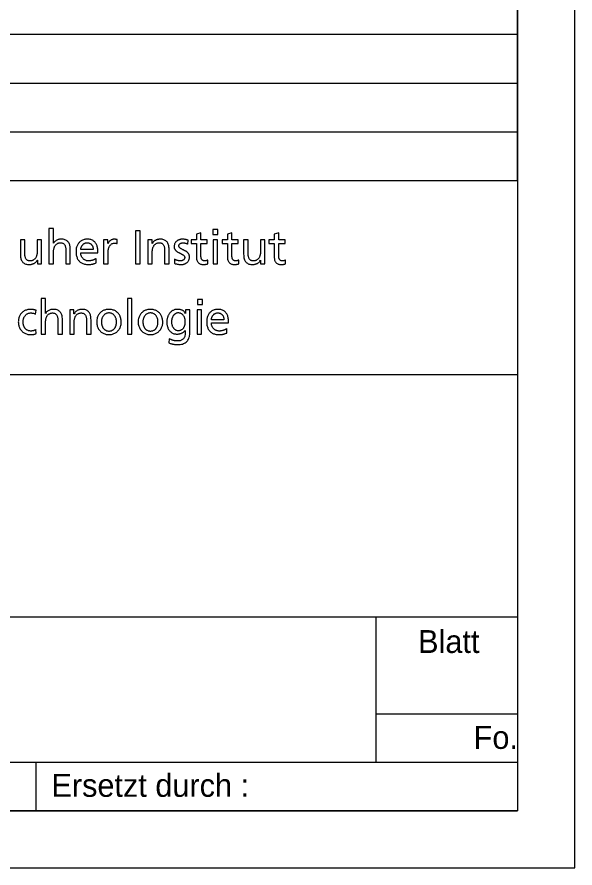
# Model space of a CAD drawing. Extents: x 0 to 210, y 0 to 148.
# Drawn here: x 198.08 to 210.25, y 0 to 18.56 of the extents above; entities that cross this region are included whole.
import ezdxf

# ---------------------------------------------------------------- set-up
doc = ezdxf.new("R2010")
doc.units = 0
doc.layers.add('90_Plankopf', color=7, linetype='Continuous')

msp = doc.modelspace()

# ---------------------------------------------------------------- linework, layer by layer
at = {"layer": '90_Plankopf'}
for p, q in [((209, 14.998), (209, 28.745)), ((164.53, 18.185), (209, 18.185)), ((164.53, 17.123), (209, 17.123)), ((164.53, 16.06), (209, 16.06)), ((164.53, 14.998), (209, 14.998)), ((164.53, 14.998), (209, 14.998)), ((209, 14.998), (209, 1.25)), ((209, 14.998), (209, 1.25)), ((200.264, 13.621), (200.264, 13.708)), ((201.808, 13.61), (201.816, 13.694)), ((199.743, 13.49), (199.471, 13.49)), ((199.471, 13.418), (199.846, 13.418)), ((199.806, 13.198), (199.806, 13.295)), ((201.518, 13.28), (201.513, 13.193)), ((202.24, 13.179), (202.24, 13.261)), ((202.916, 13.179), (202.916, 13.261)), ((203.936, 13.179), (203.936, 13.261)), ((198.488, 12.084), (198.496, 12.165)), ((202.593, 11.96), (202.321, 11.96)), ((202.321, 11.888), (202.696, 11.888)), ((198.5, 11.656), (198.493, 11.743)), ((202.656, 11.668), (202.656, 11.765)), ((201.399, 11.543), (201.389, 11.454)), ((188, 10.768), (209, 10.768)), ((188, 5.48), (209, 5.48)), ((205.912, 2.308), (205.912, 5.48)), ((205.912, 3.365), (209, 3.365)), ((188, 2.308), (209, 2.308)), ((198.5, 1.25), (198.5, 2.308)), ((209, 1.25), (164.53, 1.25)), ((167.45, 1.25), (209, 1.25)), ((167.45, 1.25), (209, 1.25))]:
    msp.add_line(p, q, dxfattribs=at)
for points in [[(0, 0), (210.25, 0), (210.25, 148.5), (0, 148.5)], [(6.25, 147.25), (209, 147.25), (209, 1.25), (6.25, 1.25)]]:
    msp.add_lwpolyline(points, close=True, dxfattribs=at)
for points in [[(198.877, 13.627), (198.875, 13.627), (198.875, 13.95), (198.778, 13.95), (198.778, 13.176), (198.875, 13.176), (198.875, 13.42)], [(202.463, 13.82), (202.463, 13.93), (202.354, 13.93), (202.354, 13.82), (202.463, 13.82)], [(200.662, 13.176), (200.765, 13.176), (200.765, 13.897), (200.662, 13.897), (200.662, 13.176)], [(202.093, 13.336), (202.093, 13.624), (202.232, 13.624), (202.232, 13.703), (202.093, 13.703), (202.093, 13.855), (201.996, 13.824), (201.996, 13.703), (201.877, 13.703), (201.877, 13.624), (201.996, 13.624), (201.996, 13.317)], [(202.769, 13.336), (202.769, 13.624), (202.908, 13.624), (202.908, 13.703), (202.769, 13.703), (202.769, 13.855), (202.672, 13.824), (202.672, 13.703), (202.553, 13.703), (202.553, 13.624), (202.672, 13.624), (202.672, 13.317)], [(203.788, 13.336), (203.788, 13.624), (203.928, 13.624), (203.928, 13.703), (203.788, 13.703), (203.788, 13.855), (203.691, 13.824), (203.691, 13.703), (203.573, 13.703), (203.573, 13.624), (203.691, 13.624), (203.691, 13.317)], [(198.251, 13.43), (198.251, 13.703), (198.154, 13.703), (198.154, 13.39)], [(198.523, 13.26), (198.525, 13.26), (198.525, 13.176), (198.619, 13.176), (198.619, 13.703), (198.522, 13.703), (198.522, 13.459)], [(200.063, 13.621), (200.061, 13.621), (200.061, 13.703), (199.97, 13.703), (199.97, 13.176), (200.067, 13.176), (200.067, 13.416)], [(201.029, 13.619), (201.027, 13.619), (201.027, 13.703), (200.933, 13.703), (200.933, 13.176), (201.03, 13.176), (201.03, 13.42)], [(202.36, 13.703), (202.36, 13.176), (202.457, 13.176), (202.457, 13.703), (202.36, 13.703)], [(203.121, 13.43), (203.121, 13.703), (203.024, 13.703), (203.024, 13.39)], [(203.393, 13.26), (203.395, 13.26), (203.395, 13.176), (203.489, 13.176), (203.489, 13.703), (203.392, 13.703), (203.392, 13.459)], [(199.147, 13.449), (199.147, 13.176), (199.244, 13.176), (199.244, 13.489)], [(201.301, 13.449), (201.301, 13.176), (201.398, 13.176), (201.398, 13.489)], [(198.705, 12.097), (198.703, 12.097), (198.703, 12.42), (198.606, 12.42), (198.606, 11.647), (198.703, 11.647), (198.703, 11.89)], [(200.491, 11.647), (200.588, 11.647), (200.588, 12.42), (200.491, 12.42), (200.491, 11.647)], [(202.123, 12.29), (202.123, 12.4), (202.014, 12.4), (202.014, 12.29), (202.123, 12.29)], [(199.326, 12.089), (199.324, 12.089), (199.324, 12.173), (199.23, 12.173), (199.23, 11.647), (199.327, 11.647), (199.327, 11.89)], [(201.849, 11.669), (201.849, 12.173), (201.759, 12.173), (201.759, 12.094), (201.757, 12.094)], [(202.008, 12.173), (202.008, 11.647), (202.105, 11.647), (202.105, 12.173), (202.008, 12.173)], [(198.974, 11.919), (198.974, 11.647), (199.071, 11.647), (199.071, 11.959)], [(199.598, 11.919), (199.598, 11.647), (199.695, 11.647), (199.695, 11.959)], [(201.75, 11.728), (201.752, 11.728), (201.752, 11.677)]]:
    msp.add_lwpolyline(points, dxfattribs=at)
for points in [[(198.875, 13.42), (198.875, 13.452), (198.878, 13.481), (198.885, 13.508), (198.891, 13.534), (198.901, 13.557), (198.914, 13.576), (198.927, 13.595), (198.944, 13.61), (198.964, 13.621), (198.984, 13.631), (199.008, 13.636), (199.035, 13.637), (199.063, 13.635), (199.085, 13.627), (199.102, 13.613), (199.118, 13.599), (199.13, 13.578), (199.137, 13.551), (199.144, 13.524), (199.147, 13.49), (199.147, 13.449)], [(199.244, 13.489), (199.244, 13.536), (199.237, 13.577), (199.223, 13.61), (199.209, 13.644), (199.187, 13.67), (199.158, 13.688), (199.129, 13.706), (199.092, 13.715), (199.047, 13.715), (199.01, 13.715), (198.977, 13.707), (198.948, 13.692), (198.919, 13.677), (198.895, 13.655), (198.877, 13.627)], [(199.846, 13.418), (199.846, 13.46), (199.842, 13.5), (199.835, 13.536), (199.827, 13.572), (199.814, 13.603), (199.796, 13.63), (199.778, 13.657), (199.754, 13.677), (199.724, 13.692), (199.695, 13.707), (199.658, 13.715), (199.614, 13.715), (199.577, 13.715), (199.543, 13.708), (199.513, 13.695), (199.483, 13.682), (199.457, 13.664), (199.435, 13.64), (199.414, 13.617), (199.397, 13.589), (199.385, 13.556), (199.374, 13.524), (199.368, 13.488), (199.368, 13.449), (199.368, 13.406), (199.373, 13.367), (199.384, 13.332), (199.395, 13.297), (199.411, 13.267), (199.434, 13.242), (199.456, 13.217), (199.484, 13.198), (199.519, 13.184), (199.553, 13.171), (199.593, 13.164), (199.64, 13.164), (199.669, 13.164), (199.693, 13.166), (199.713, 13.17), (199.733, 13.174), (199.751, 13.178), (199.766, 13.183), (199.78, 13.188), (199.794, 13.193), (199.806, 13.198)], [(199.471, 13.49), (199.472, 13.507), (199.476, 13.524), (199.483, 13.542), (199.489, 13.559), (199.497, 13.574), (199.509, 13.589), (199.52, 13.603), (199.534, 13.615), (199.551, 13.623), (199.568, 13.632), (199.588, 13.636), (199.612, 13.637), (199.633, 13.636), (199.652, 13.633), (199.668, 13.625), (199.684, 13.617), (199.698, 13.607), (199.709, 13.594), (199.72, 13.58), (199.729, 13.564), (199.734, 13.547), (199.74, 13.529), (199.743, 13.51), (199.743, 13.49)], [(200.264, 13.708), (200.258, 13.709), (200.251, 13.71), (200.245, 13.712), (200.239, 13.713), (200.232, 13.713), (200.225, 13.714), (200.218, 13.715), (200.21, 13.715), (200.2, 13.715), (200.182, 13.715), (200.163, 13.711), (200.146, 13.703), (200.128, 13.695), (200.112, 13.684), (200.098, 13.67), (200.083, 13.656), (200.072, 13.639), (200.063, 13.621)], [(200.067, 13.416), (200.067, 13.46), (200.073, 13.498), (200.085, 13.53), (200.097, 13.562), (200.113, 13.587), (200.135, 13.604), (200.156, 13.621), (200.182, 13.63), (200.211, 13.63), (200.219, 13.631), (200.228, 13.63), (200.237, 13.629), (200.246, 13.627), (200.255, 13.625), (200.264, 13.621)], [(201.398, 13.489), (201.398, 13.536), (201.391, 13.577), (201.377, 13.61), (201.364, 13.644), (201.342, 13.67), (201.313, 13.688), (201.284, 13.706), (201.247, 13.715), (201.201, 13.715), (201.177, 13.715), (201.153, 13.711), (201.13, 13.704), (201.108, 13.696), (201.088, 13.685), (201.07, 13.67), (201.053, 13.656), (201.039, 13.639), (201.029, 13.619)], [(201.03, 13.42), (201.03, 13.452), (201.033, 13.481), (201.039, 13.508), (201.046, 13.534), (201.055, 13.557), (201.069, 13.576), (201.082, 13.595), (201.098, 13.61), (201.118, 13.621), (201.138, 13.631), (201.162, 13.636), (201.19, 13.637), (201.218, 13.635), (201.24, 13.627), (201.256, 13.613), (201.273, 13.599), (201.284, 13.578), (201.291, 13.551), (201.298, 13.524), (201.301, 13.49), (201.301, 13.449)], [(201.816, 13.694), (201.797, 13.7), (201.778, 13.705), (201.759, 13.709), (201.739, 13.713), (201.718, 13.715), (201.696, 13.715), (201.669, 13.715), (201.645, 13.712), (201.623, 13.705), (201.6, 13.698), (201.581, 13.688), (201.564, 13.675), (201.547, 13.662), (201.534, 13.645), (201.524, 13.625), (201.515, 13.604), (201.51, 13.58), (201.51, 13.553), (201.51, 13.532), (201.514, 13.514), (201.523, 13.498), (201.531, 13.483), (201.541, 13.47), (201.555, 13.459), (201.569, 13.447), (201.583, 13.437), (201.6, 13.429), (201.616, 13.42), (201.632, 13.412), (201.648, 13.404), (201.664, 13.397), (201.679, 13.389), (201.693, 13.38), (201.706, 13.373), (201.717, 13.363), (201.725, 13.353), (201.733, 13.343), (201.738, 13.331), (201.738, 13.318), (201.738, 13.304), (201.735, 13.292), (201.729, 13.282), (201.723, 13.272), (201.715, 13.265), (201.705, 13.259), (201.695, 13.253), (201.685, 13.249), (201.673, 13.246), (201.662, 13.244), (201.65, 13.242), (201.639, 13.242), (201.629, 13.242), (201.617, 13.244), (201.604, 13.247), (201.59, 13.249), (201.575, 13.253), (201.56, 13.259), (201.545, 13.265), (201.531, 13.271), (201.518, 13.28)], [(201.513, 13.193), (201.535, 13.181), (201.559, 13.174), (201.583, 13.17), (201.608, 13.166), (201.632, 13.164), (201.657, 13.164), (201.681, 13.164), (201.704, 13.167), (201.726, 13.174), (201.747, 13.18), (201.767, 13.191), (201.784, 13.204), (201.802, 13.217), (201.815, 13.234), (201.826, 13.255), (201.836, 13.276), (201.841, 13.3), (201.841, 13.328), (201.841, 13.352), (201.837, 13.372), (201.828, 13.389), (201.82, 13.406), (201.809, 13.42), (201.796, 13.431), (201.782, 13.443), (201.767, 13.453), (201.751, 13.461), (201.735, 13.469), (201.719, 13.477), (201.703, 13.484), (201.687, 13.491), (201.672, 13.499), (201.658, 13.507), (201.645, 13.515), (201.634, 13.524), (201.626, 13.534), (201.617, 13.545), (201.613, 13.557), (201.613, 13.573), (201.613, 13.587), (201.618, 13.599), (201.626, 13.609), (201.635, 13.618), (201.646, 13.625), (201.66, 13.63), (201.674, 13.634), (201.689, 13.637), (201.706, 13.637), (201.712, 13.637), (201.719, 13.636), (201.728, 13.634), (201.738, 13.633), (201.747, 13.631), (201.757, 13.628), (201.768, 13.626), (201.777, 13.623), (201.786, 13.62), (201.795, 13.616), (201.802, 13.613), (201.808, 13.61)], [(198.154, 13.39), (198.154, 13.343), (198.161, 13.302), (198.175, 13.269), (198.189, 13.235), (198.21, 13.209), (198.24, 13.191), (198.269, 13.173), (198.306, 13.164), (198.351, 13.164), (198.376, 13.164), (198.399, 13.168), (198.422, 13.176), (198.444, 13.183), (198.465, 13.194), (198.482, 13.209), (198.5, 13.223), (198.514, 13.24), (198.523, 13.26)], [(198.522, 13.459), (198.522, 13.427), (198.519, 13.398), (198.513, 13.371), (198.507, 13.345), (198.497, 13.322), (198.484, 13.303), (198.471, 13.284), (198.454, 13.269), (198.434, 13.258), (198.414, 13.248), (198.39, 13.243), (198.362, 13.242), (198.334, 13.244), (198.312, 13.252), (198.296, 13.266), (198.28, 13.28), (198.268, 13.301), (198.261, 13.328), (198.254, 13.355), (198.251, 13.389), (198.251, 13.43)], [(199.806, 13.295), (199.8, 13.29), (199.791, 13.285), (199.78, 13.279), (199.768, 13.273), (199.755, 13.267), (199.74, 13.261), (199.725, 13.256), (199.71, 13.251), (199.693, 13.248), (199.677, 13.244), (199.66, 13.243), (199.644, 13.242), (199.621, 13.243), (199.599, 13.247), (199.578, 13.255), (199.558, 13.264), (199.539, 13.276), (199.523, 13.291), (199.507, 13.307), (199.494, 13.325), (199.485, 13.347), (199.476, 13.368), (199.471, 13.392), (199.471, 13.418)], [(203.024, 13.39), (203.024, 13.343), (203.031, 13.302), (203.045, 13.269), (203.059, 13.235), (203.08, 13.209), (203.109, 13.191), (203.138, 13.173), (203.176, 13.164), (203.221, 13.164), (203.245, 13.164), (203.269, 13.168), (203.292, 13.176), (203.314, 13.183), (203.334, 13.194), (203.352, 13.209), (203.37, 13.223), (203.383, 13.24), (203.393, 13.26)], [(203.392, 13.459), (203.392, 13.427), (203.389, 13.398), (203.383, 13.371), (203.376, 13.345), (203.367, 13.322), (203.354, 13.303), (203.341, 13.284), (203.324, 13.269), (203.304, 13.258), (203.284, 13.248), (203.26, 13.243), (203.232, 13.242), (203.204, 13.244), (203.182, 13.252), (203.166, 13.266), (203.149, 13.28), (203.138, 13.301), (203.131, 13.328), (203.124, 13.355), (203.121, 13.389), (203.121, 13.43)], [(201.996, 13.317), (201.996, 13.282), (202.003, 13.253), (202.016, 13.23), (202.029, 13.208), (202.047, 13.191), (202.071, 13.18), (202.096, 13.169), (202.124, 13.164), (202.158, 13.164), (202.174, 13.164), (202.188, 13.166), (202.203, 13.169), (202.217, 13.172), (202.229, 13.175), (202.24, 13.179)], [(202.24, 13.261), (202.233, 13.256), (202.224, 13.252), (202.213, 13.248), (202.202, 13.245), (202.189, 13.243), (202.174, 13.242), (202.159, 13.242), (202.146, 13.246), (202.133, 13.253), (202.121, 13.261), (202.111, 13.271), (202.104, 13.285), (202.097, 13.299), (202.093, 13.316), (202.093, 13.336)], [(202.672, 13.317), (202.672, 13.282), (202.679, 13.253), (202.692, 13.23), (202.705, 13.208), (202.723, 13.191), (202.747, 13.18), (202.772, 13.169), (202.8, 13.164), (202.834, 13.164), (202.85, 13.164), (202.864, 13.166), (202.879, 13.169), (202.893, 13.172), (202.905, 13.175), (202.916, 13.179)], [(202.916, 13.261), (202.909, 13.256), (202.9, 13.252), (202.889, 13.248), (202.878, 13.245), (202.865, 13.243), (202.85, 13.242), (202.835, 13.242), (202.822, 13.246), (202.809, 13.253), (202.797, 13.261), (202.787, 13.271), (202.78, 13.285), (202.773, 13.299), (202.769, 13.316), (202.769, 13.336)], [(203.691, 13.317), (203.692, 13.282), (203.698, 13.253), (203.711, 13.23), (203.724, 13.208), (203.743, 13.191), (203.767, 13.18), (203.791, 13.169), (203.82, 13.164), (203.853, 13.164), (203.869, 13.164), (203.884, 13.166), (203.898, 13.169), (203.912, 13.172), (203.925, 13.175), (203.936, 13.179)], [(203.936, 13.261), (203.929, 13.256), (203.92, 13.252), (203.909, 13.248), (203.898, 13.245), (203.885, 13.243), (203.87, 13.242), (203.855, 13.242), (203.841, 13.246), (203.829, 13.253), (203.817, 13.261), (203.807, 13.271), (203.8, 13.285), (203.792, 13.299), (203.789, 13.316), (203.788, 13.336)], [(198.496, 12.165), (198.487, 12.168), (198.475, 12.172), (198.462, 12.175), (198.449, 12.178), (198.435, 12.181), (198.42, 12.182), (198.406, 12.184), (198.392, 12.185), (198.378, 12.185), (198.338, 12.185), (198.301, 12.178), (198.269, 12.165), (198.236, 12.151), (198.208, 12.132), (198.184, 12.107), (198.16, 12.083), (198.142, 12.054), (198.129, 12.02), (198.117, 11.987), (198.11, 11.95), (198.11, 11.91), (198.11, 11.872), (198.117, 11.836), (198.13, 11.803), (198.143, 11.77), (198.161, 11.741), (198.185, 11.716), (198.209, 11.69), (198.237, 11.67), (198.269, 11.656), (198.302, 11.642), (198.339, 11.635), (198.378, 11.634), (198.39, 11.634), (198.403, 11.635), (198.417, 11.636), (198.43, 11.637), (198.444, 11.639), (198.459, 11.642), (198.473, 11.645), (198.487, 11.65), (198.5, 11.656)], [(198.493, 11.743), (198.483, 11.736), (198.472, 11.73), (198.46, 11.726), (198.448, 11.722), (198.436, 11.718), (198.424, 11.716), (198.412, 11.714), (198.4, 11.713), (198.389, 11.713), (198.364, 11.713), (198.342, 11.717), (198.323, 11.724), (198.303, 11.732), (198.287, 11.742), (198.273, 11.755), (198.259, 11.768), (198.248, 11.783), (198.239, 11.8), (198.23, 11.817), (198.224, 11.834), (198.22, 11.853), (198.215, 11.872), (198.213, 11.891), (198.213, 11.91), (198.213, 11.935), (198.217, 11.959), (198.225, 11.983), (198.232, 12.006), (198.243, 12.027), (198.257, 12.046), (198.272, 12.064), (198.289, 12.079), (198.31, 12.09), (198.331, 12.101), (198.355, 12.107), (198.383, 12.107), (198.398, 12.107), (198.415, 12.105), (198.433, 12.101), (198.451, 12.097), (198.469, 12.092), (198.488, 12.084)], [(198.703, 11.89), (198.703, 11.922), (198.706, 11.951), (198.712, 11.978), (198.718, 12.004), (198.728, 12.027), (198.741, 12.046), (198.754, 12.066), (198.771, 12.08), (198.791, 12.091), (198.811, 12.101), (198.835, 12.107), (198.862, 12.107), (198.89, 12.105), (198.913, 12.097), (198.929, 12.083), (198.945, 12.069), (198.957, 12.048), (198.964, 12.021), (198.971, 11.994), (198.974, 11.96), (198.974, 11.919)], [(199.071, 11.959), (199.071, 12.006), (199.064, 12.047), (199.05, 12.081), (199.036, 12.114), (199.014, 12.14), (198.985, 12.158), (198.956, 12.176), (198.919, 12.185), (198.874, 12.185), (198.837, 12.185), (198.804, 12.177), (198.775, 12.162), (198.746, 12.147), (198.722, 12.125), (198.705, 12.097)], [(199.695, 11.959), (199.695, 12.006), (199.688, 12.047), (199.674, 12.081), (199.66, 12.114), (199.639, 12.14), (199.61, 12.158), (199.581, 12.176), (199.543, 12.185), (199.498, 12.185), (199.474, 12.185), (199.45, 12.181), (199.427, 12.174), (199.405, 12.166), (199.385, 12.155), (199.367, 12.141), (199.349, 12.126), (199.336, 12.109), (199.326, 12.089)], [(199.327, 11.89), (199.327, 11.922), (199.33, 11.951), (199.336, 11.978), (199.343, 12.004), (199.352, 12.027), (199.365, 12.046), (199.378, 12.066), (199.395, 12.08), (199.415, 12.091), (199.435, 12.101), (199.459, 12.107), (199.487, 12.107), (199.515, 12.105), (199.537, 12.097), (199.553, 12.083), (199.57, 12.069), (199.581, 12.048), (199.588, 12.021), (199.595, 11.994), (199.598, 11.96), (199.598, 11.919)], [(200.349, 11.973), (200.345, 11.989), (200.341, 12.005), (200.335, 12.02), (200.323, 12.054), (200.305, 12.083), (200.281, 12.107), (200.257, 12.132), (200.229, 12.151), (200.197, 12.165), (200.164, 12.178), (200.127, 12.185), (200.087, 12.185), (200.047, 12.185), (200.01, 12.178), (199.977, 12.165), (199.945, 12.151), (199.916, 12.132), (199.893, 12.107), (199.869, 12.083), (199.851, 12.054), (199.838, 12.02), (199.826, 11.987), (199.819, 11.95), (199.819, 11.91)], [(199.922, 11.91), (199.922, 11.935), (199.926, 11.959), (199.933, 11.983), (199.941, 12.006), (199.952, 12.027), (199.966, 12.046), (199.98, 12.064), (199.997, 12.079), (200.018, 12.09), (200.038, 12.101), (200.061, 12.107), (200.087, 12.107), (200.113, 12.107), (200.136, 12.101), (200.156, 12.09), (200.177, 12.079), (200.194, 12.064), (200.208, 12.046), (200.222, 12.027), (200.233, 12.006), (200.24, 11.983), (200.248, 11.959), (200.251, 11.935), (200.251, 11.91), (200.251, 11.891), (200.249, 11.872), (200.245, 11.853), (200.241, 11.834), (200.235, 11.817), (200.226, 11.8), (200.218, 11.783), (200.207, 11.768), (200.194, 11.755), (200.181, 11.742), (200.166, 11.732), (200.148, 11.724), (200.13, 11.717), (200.11, 11.713), (200.087, 11.713), (200.064, 11.713), (200.044, 11.717), (200.026, 11.724), (200.008, 11.732), (199.993, 11.742), (199.98, 11.755), (199.967, 11.768), (199.956, 11.783), (199.947, 11.8), (199.939, 11.817), (199.933, 11.834), (199.928, 11.853), (199.924, 11.872), (199.922, 11.891), (199.922, 11.91)], [(201.254, 11.973), (201.251, 11.989), (201.246, 12.005), (201.24, 12.02), (201.228, 12.054), (201.21, 12.083), (201.186, 12.107), (201.162, 12.132), (201.134, 12.151), (201.102, 12.165), (201.069, 12.178), (201.032, 12.185), (200.992, 12.185), (200.952, 12.185), (200.915, 12.178), (200.883, 12.165), (200.85, 12.151), (200.822, 12.132), (200.798, 12.107), (200.774, 12.083), (200.756, 12.054), (200.743, 12.02), (200.731, 11.987), (200.724, 11.95), (200.724, 11.91)], [(200.827, 11.91), (200.827, 11.935), (200.831, 11.959), (200.838, 11.983), (200.846, 12.006), (200.857, 12.027), (200.871, 12.046), (200.885, 12.064), (200.902, 12.079), (200.923, 12.09), (200.943, 12.101), (200.966, 12.107), (200.992, 12.107), (201.018, 12.107), (201.041, 12.101), (201.062, 12.09), (201.082, 12.079), (201.099, 12.064), (201.113, 12.046), (201.127, 12.027), (201.138, 12.006), (201.145, 11.983), (201.153, 11.959), (201.156, 11.935), (201.156, 11.91), (201.156, 11.891), (201.154, 11.872), (201.15, 11.853), (201.146, 11.834), (201.14, 11.817), (201.131, 11.8), (201.123, 11.783), (201.112, 11.768), (201.099, 11.755), (201.086, 11.742), (201.071, 11.732), (201.053, 11.724), (201.035, 11.717), (201.015, 11.713), (200.992, 11.713), (200.969, 11.713), (200.949, 11.717), (200.931, 11.724), (200.913, 11.732), (200.898, 11.742), (200.885, 11.755), (200.872, 11.768), (200.861, 11.783), (200.852, 11.8), (200.844, 11.817), (200.838, 11.834), (200.833, 11.853), (200.829, 11.872), (200.827, 11.891), (200.827, 11.91)], [(201.757, 12.094), (201.747, 12.113), (201.735, 12.13), (201.72, 12.143), (201.705, 12.157), (201.686, 12.167), (201.663, 12.174), (201.641, 12.181), (201.614, 12.185), (201.584, 12.185), (201.552, 12.185), (201.523, 12.18), (201.498, 12.169), (201.473, 12.158), (201.451, 12.144), (201.432, 12.126), (201.413, 12.107), (201.398, 12.086), (201.385, 12.062), (201.373, 12.039), (201.364, 12.013), (201.358, 11.987), (201.352, 11.96), (201.348, 11.933), (201.348, 11.906), (201.348, 11.871), (201.353, 11.839), (201.362, 11.808), (201.372, 11.777), (201.386, 11.749), (201.405, 11.725), (201.423, 11.701), (201.446, 11.682), (201.475, 11.668), (201.503, 11.654), (201.536, 11.647), (201.573, 11.647), (201.596, 11.647), (201.618, 11.65), (201.64, 11.656), (201.661, 11.662), (201.682, 11.671), (201.701, 11.683), (201.719, 11.695), (201.736, 11.71), (201.75, 11.728)], [(201.598, 11.725), (201.575, 11.725), (201.555, 11.73), (201.537, 11.74), (201.519, 11.75), (201.503, 11.764), (201.491, 11.781), (201.478, 11.798), (201.468, 11.818), (201.462, 11.84), (201.455, 11.862), (201.452, 11.886), (201.452, 11.911), (201.452, 11.929), (201.453, 11.947), (201.457, 11.966), (201.461, 11.984), (201.467, 12.002), (201.475, 12.018), (201.483, 12.035), (201.492, 12.05), (201.504, 12.064), (201.516, 12.077), (201.53, 12.087), (201.545, 12.095), (201.561, 12.103), (201.579, 12.107), (201.598, 12.107), (201.624, 12.107), (201.646, 12.101), (201.666, 12.09), (201.685, 12.08), (201.701, 12.065), (201.714, 12.046), (201.726, 12.027), (201.736, 12.006), (201.742, 11.981), (201.749, 11.957), (201.752, 11.931), (201.752, 11.903), (201.752, 11.879), (201.748, 11.856), (201.741, 11.834), (201.733, 11.813), (201.723, 11.794), (201.709, 11.777), (201.695, 11.761), (201.679, 11.748), (201.66, 11.739), (201.642, 11.73), (201.621, 11.725), (201.598, 11.725)], [(202.696, 11.888), (202.696, 11.931), (202.693, 11.97), (202.685, 12.006), (202.677, 12.042), (202.664, 12.073), (202.646, 12.1), (202.628, 12.127), (202.604, 12.148), (202.574, 12.162), (202.545, 12.177), (202.508, 12.185), (202.464, 12.185), (202.427, 12.185), (202.393, 12.178), (202.363, 12.166), (202.333, 12.152), (202.307, 12.134), (202.285, 12.111), (202.264, 12.087), (202.247, 12.059), (202.235, 12.026), (202.224, 11.994), (202.218, 11.958), (202.218, 11.919), (202.218, 11.876), (202.223, 11.837), (202.234, 11.802), (202.245, 11.767), (202.261, 11.737), (202.284, 11.712), (202.306, 11.687), (202.334, 11.668), (202.369, 11.655), (202.403, 11.641), (202.443, 11.634), (202.49, 11.634), (202.519, 11.634), (202.543, 11.636), (202.563, 11.64), (202.584, 11.644), (202.601, 11.648), (202.616, 11.653), (202.63, 11.659), (202.644, 11.664), (202.656, 11.668)], [(202.321, 11.96), (202.323, 11.977), (202.326, 11.995), (202.333, 12.012), (202.339, 12.029), (202.347, 12.045), (202.359, 12.059), (202.37, 12.073), (202.384, 12.085), (202.401, 12.093), (202.418, 12.102), (202.438, 12.107), (202.462, 12.107), (202.483, 12.107), (202.502, 12.103), (202.518, 12.095), (202.534, 12.088), (202.548, 12.077), (202.559, 12.064), (202.57, 12.05), (202.579, 12.035), (202.584, 12.017), (202.59, 11.999), (202.593, 11.981), (202.593, 11.96)], [(199.819, 11.91), (199.819, 11.872), (199.826, 11.836), (199.839, 11.803), (199.852, 11.77), (199.87, 11.741), (199.894, 11.716), (199.917, 11.69), (199.946, 11.67), (199.978, 11.656), (200.011, 11.642), (200.047, 11.635), (200.087, 11.634), (200.127, 11.635), (200.163, 11.642), (200.196, 11.656), (200.228, 11.67), (200.257, 11.69), (200.28, 11.716), (200.304, 11.741), (200.322, 11.77), (200.335, 11.803), (200.348, 11.836), (200.354, 11.872), (200.354, 11.91), (200.354, 11.932), (200.352, 11.953), (200.349, 11.973)], [(200.724, 11.91), (200.724, 11.872), (200.731, 11.836), (200.744, 11.803), (200.757, 11.77), (200.775, 11.741), (200.799, 11.716), (200.822, 11.69), (200.851, 11.67), (200.883, 11.656), (200.916, 11.642), (200.952, 11.635), (200.992, 11.634), (201.032, 11.635), (201.068, 11.642), (201.101, 11.656), (201.133, 11.67), (201.162, 11.69), (201.185, 11.716), (201.209, 11.741), (201.227, 11.77), (201.24, 11.803), (201.253, 11.836), (201.259, 11.872), (201.26, 11.91), (201.259, 11.932), (201.258, 11.953), (201.254, 11.973)], [(202.656, 11.765), (202.65, 11.76), (202.641, 11.755), (202.63, 11.749), (202.618, 11.743), (202.605, 11.737), (202.59, 11.732), (202.575, 11.726), (202.56, 11.722), (202.543, 11.718), (202.527, 11.715), (202.51, 11.713), (202.494, 11.713), (202.471, 11.713), (202.449, 11.717), (202.428, 11.725), (202.408, 11.734), (202.389, 11.746), (202.373, 11.761), (202.357, 11.777), (202.344, 11.795), (202.335, 11.817), (202.326, 11.838), (202.321, 11.862), (202.321, 11.888)], [(201.389, 11.454), (201.417, 11.444), (201.441, 11.437), (201.463, 11.431), (201.484, 11.426), (201.504, 11.423), (201.523, 11.42), (201.541, 11.418), (201.559, 11.418), (201.578, 11.418), (201.64, 11.418), (201.692, 11.428), (201.732, 11.447), (201.772, 11.467), (201.801, 11.495), (201.82, 11.533), (201.84, 11.57), (201.849, 11.616), (201.849, 11.669)], [(201.752, 11.677), (201.752, 11.639), (201.745, 11.607), (201.732, 11.58), (201.719, 11.553), (201.701, 11.533), (201.677, 11.518), (201.652, 11.504), (201.623, 11.496), (201.589, 11.496), (201.571, 11.496), (201.555, 11.497), (201.54, 11.499), (201.524, 11.5), (201.51, 11.503), (201.495, 11.507), (201.48, 11.511), (201.466, 11.516), (201.45, 11.522), (201.434, 11.528), (201.417, 11.535), (201.399, 11.543)]]:
    msp.add_open_spline(points, degree=3, dxfattribs=at)

# ---------------------------------------------------------------- texts
for s, p in [('Blatt', (206.829, 4.69)), ('Fo.', (208.04, 2.598)), ('Ersetzt durch :', (198.832, 1.552))]:
    msp.add_text(s, height=0.5, dxfattribs=at).set_placement(p)

doc.saveas('drawing.dxf')
